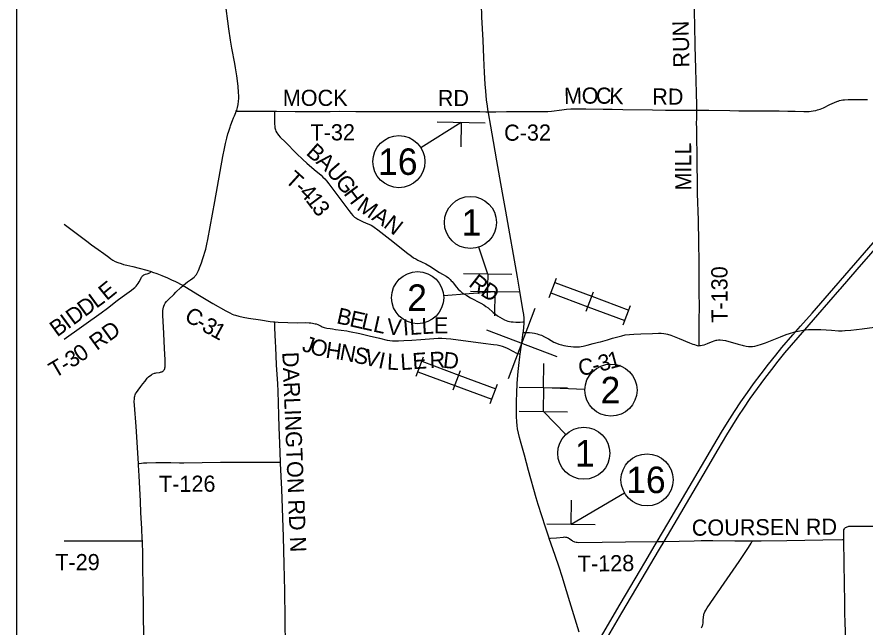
# Model space of a CAD drawing. Extents: x 40529 to 41139, y 15164 to 15584.
# Drawn here: x 40528.7 to 40618.2, y 15358.4 to 15422.8 of the extents above; entities that cross this region are included whole.
import ezdxf

# ---------------------------------------------------------------- set-up
doc = ezdxf.new("R2010")
doc.units = 0
for name, color, linetype in [('Default', 7, 'Continuous'), ('GM_X_County_Road', 7, 'Continuous'), ('GM_X_County_Road_Text', 7, 'Continuous'), ('GM_X_Interstate_Route', 7, 'Continuous'), ('GM_X_State_Route', 7, 'Continuous'), ('GM_X_Township_Road', 7, 'Continuous'), ('GM_X_Township_Road_Text', 7, 'Continuous'), ('SC_Scratch1', 7, 'Continuous'), ('SH_Data', 7, 'Continuous'), ('SH_Text', 7, 'Continuous')]:
    doc.layers.add(name, color=color, linetype=linetype)

msp = doc.modelspace()

# ---------------------------------------------------------------- linework, layer by layer
at = {"layer": 'Default'}
for p, q in [((40578.106, 15411.64), (40573.011, 15411.722)), ((40575.559, 15411.681), (40575.518, 15409.134)), ((40580.908, 15395.642), (40575.812, 15395.724)), ((40578.36, 15395.683), (40578.319, 15393.135)), ((40584.861, 15393.226), (40585.613, 15395.258)), ((40585.439, 15394.789), (40589.347, 15393.343)), ((40581.654, 15393.775), (40576.559, 15393.857)), ((40579.106, 15393.816), (40579.066, 15391.269)), ((40585.034, 15393.695), (40588.942, 15392.249)), ((40588.768, 15391.78), (40589.52, 15393.812)), ((40589.347, 15393.343), (40593.254, 15391.896)), ((40592.682, 15390.331), (40593.434, 15392.363)), ((40588.942, 15392.249), (40592.849, 15390.802)), ((40570.813, 15384.915), (40571.565, 15386.947)), ((40571.392, 15386.478), (40575.299, 15385.032)), ((40584.244, 15383.705), (40584.285, 15386.253)), ((40570.987, 15385.384), (40574.894, 15383.938)), ((40574.72, 15383.469), (40575.473, 15385.501)), ((40575.299, 15385.032), (40579.207, 15383.585)), ((40574.894, 15383.938), (40578.801, 15382.491)), ((40578.634, 15382.02), (40579.386, 15384.052)), ((40581.696, 15383.746), (40586.791, 15383.665)), ((40584.244, 15381.174), (40584.285, 15383.722)), ((40581.696, 15381.215), (40586.791, 15381.133)), ((40587.168, 15369.284), (40587.209, 15371.832)), ((40584.62, 15369.325), (40589.716, 15369.243))]:
    msp.add_line(p, q, dxfattribs=at)
at = {"layer": 'GM_X_County_Road'}
for points in [[(40600.43, 15413), (40601.705, 15412.989), (40603.934, 15412.954), (40604.865, 15412.943), (40605.796, 15412.943), (40606.821, 15412.939), (40609.142, 15412.923), (40610.071, 15412.895), (40610.816, 15412.889), (40611.748, 15412.871), (40612.304, 15412.876), (40612.744, 15412.915), (40613.017, 15412.968), (40613.199, 15413.018), (40613.464, 15413.112), (40613.808, 15413.26), (40614.48, 15413.582), (40614.988, 15413.813), (40615.245, 15413.918), (40615.351, 15413.954)], [(40615.351, 15413.954), (40615.377, 15413.963), (40615.505, 15414.008), (40615.684, 15414.051), (40615.865, 15414.082), (40616.049, 15414.1), (40616.42, 15414.121), (40617.414, 15414.121), (40618.462, 15414.136)], [(40578.427, 15412.837), (40578.568, 15412.835), (40578.68, 15412.833), (40579.237, 15412.836), (40580.352, 15412.847), (40581.003, 15412.847), (40582.773, 15412.851), (40584.26, 15412.858), (40584.727, 15412.872), (40585.1, 15412.898), (40586.207, 15413.048), (40586.669, 15413.097), (40587.132, 15413.125), (40587.69, 15413.137), (40588.715, 15413.13), (40590.541, 15413.11), (40590.861, 15413.106), (40591.492, 15413.099), (40592.618, 15413.064), (40595.776, 15413.028), (40597.153, 15413.013), (40598.269, 15413.016), (40599.943, 15413.005), (40600.43, 15413)], [(40533.651, 15400.945), (40536.027, 15399.161), (40536.536, 15398.771), (40537.221, 15398.286), (40537.813, 15397.869), (40538.341, 15397.46), (40538.581, 15397.297), (40538.791, 15397.156), (40539.034, 15397.018), (40539.291, 15396.91), (40539.64, 15396.791), (40539.907, 15396.709), (40540.269, 15396.626), (40540.902, 15396.474), (40541.544, 15396.323), (40542.356, 15396.104), (40542.836, 15395.949)], [(40542.836, 15395.949), (40542.966, 15395.907), (40543.422, 15395.755), (40543.944, 15395.55), (40544.545, 15395.292), (40545.055, 15395.057), (40545.142, 15395.021), (40545.396, 15394.901), (40546.143, 15394.516), (40546.19, 15394.488)], [(40546.19, 15394.488), (40546.547, 15394.281), (40547.736, 15393.544), (40549.341, 15392.593), (40550.715, 15391.803), (40551.124, 15391.581), (40551.375, 15391.461), (40551.547, 15391.393), (40551.721, 15391.334), (40552.082, 15391.244), (40552.536, 15391.148), (40553.086, 15391.051), (40554.377, 15390.854), (40555.39, 15390.691), (40555.759, 15390.648), (40555.885, 15390.64)], [(40555.885, 15390.64), (40556.223, 15390.62), (40558.27, 15390.557), (40559.122, 15390.562), (40559.5, 15390.548), (40559.687, 15390.532), (40559.871, 15390.503), (40560.143, 15390.446), (40560.233, 15390.421), (40560.416, 15390.355), (40560.644, 15390.251), (40560.762, 15390.194), (40560.866, 15390.137), (40561.098, 15390.057), (40561.373, 15389.976), (40561.725, 15389.929), (40561.989, 15389.896), (40562.287, 15389.853), (40563.484, 15389.688), (40563.759, 15389.641), (40564.853, 15389.407), (40565.853, 15389.173), (40566.941, 15388.909), (40567.759, 15388.726), (40568.033, 15388.676), (40568.309, 15388.642), (40568.586, 15388.627), (40568.957, 15388.633), (40569.515, 15388.662), (40570.353, 15388.724), (40571.284, 15388.787), (40572.679, 15388.891), (40573.146, 15388.913), (40573.52, 15388.912), (40573.987, 15388.888), (40574.453, 15388.845), (40577.877, 15388.412), (40578.988, 15388.264), (40579.357, 15388.204), (40579.633, 15388.146), (40579.904, 15388.072), (40580.169, 15387.974), (40580.424, 15387.855), (40581.082, 15387.501), (40581.332, 15387.382), (40581.504, 15387.318), (40581.592, 15387.295), (40581.787, 15387.244)], [(40556.477, 15375.813), (40556.398, 15377.825), (40556.347, 15379.501), (40556.317, 15380.801), (40556.237, 15383.314), (40556.196, 15384.084), (40556.073, 15386.11), (40555.988, 15387.976), (40555.956, 15388.521), (40555.912, 15389.265), (40555.888, 15390.012), (40555.886, 15390.386), (40555.885, 15390.64)], [(40600.695, 15388.131), (40600.762, 15388.133), (40600.851, 15388.143), (40600.999, 15388.181), (40601.207, 15388.236), (40601.56, 15388.356), (40601.821, 15388.464), (40602.088, 15388.577), (40602.262, 15388.64), (40602.491, 15388.706), (40602.561, 15388.72), (40602.729, 15388.736), (40602.909, 15388.741), (40603.199, 15388.722), (40603.464, 15388.663), (40604.827, 15388.282), (40605.232, 15388.183), (40605.332, 15388.162), (40605.391, 15388.14), (40605.504, 15388.124), (40605.656, 15388.09), (40605.916, 15388.056), (40606.176, 15388.045), (40606.317, 15388.052), (40606.574, 15388.095), (40606.833, 15388.157), (40607.274, 15388.29), (40607.715, 15388.442), (40608.237, 15388.641), (40609.271, 15389.067), (40609.88, 15389.304), (40610.234, 15389.426), (40610.681, 15389.56), (40610.891, 15389.617), (40610.94, 15389.63), (40611.135, 15389.673), (40611.502, 15389.746), (40611.857, 15389.797), (40611.909, 15389.805), (40612.245, 15389.837), (40612.619, 15389.855), (40612.993, 15389.854), (40613.552, 15389.829), (40614.668, 15389.757), (40615.411, 15389.712), (40615.675, 15389.709)], [(40615.675, 15389.709), (40615.782, 15389.708), (40616.06, 15389.719), (40616.119, 15389.725)], [(40616.119, 15389.725), (40616.708, 15389.782), (40617.91, 15389.921), (40619.206, 15390.077)], [(40581.787, 15387.244), (40581.957, 15388.436), (40582.116, 15389.529)], [(40582.116, 15389.529), (40582.295, 15389.531), (40582.483, 15389.533), (40582.763, 15389.52), (40583.043, 15389.492), (40583.321, 15389.447), (40583.595, 15389.382), (40583.775, 15389.326), (40584.037, 15389.224), (40584.377, 15389.068), (40584.791, 15388.851), (40585.359, 15388.514), (40585.611, 15388.39), (40585.873, 15388.291), (40586.14, 15388.207), (40586.402, 15388.148), (40586.827, 15388.074), (40587.139, 15388.029), (40587.416, 15388.014), (40587.677, 15387.995), (40587.871, 15388.006), (40588.053, 15388.024), (40588.236, 15388.049), (40588.429, 15388.084), (40588.864, 15388.197), (40589.493, 15388.343), (40590.07, 15388.499), (40590.263, 15388.543), (40591.009, 15388.756), (40591.538, 15388.909), (40592.24, 15389.112), (40592.512, 15389.186), (40592.872, 15389.263), (40593.336, 15389.317), (40593.802, 15389.351), (40594.548, 15389.378), (40595.758, 15389.419), (40596.411, 15389.44), (40596.692, 15389.438), (40596.973, 15389.416), (40597.159, 15389.386), (40597.342, 15389.345), (40597.7, 15389.24), (40598.051, 15389.114), (40598.57, 15388.902), (40599.682, 15388.429), (40600.017, 15388.299), (40600.192, 15388.242), (40600.391, 15388.168), (40600.599, 15388.128), (40600.695, 15388.131)], [(40557.06, 15352.563), (40557.051, 15353.293), (40557.032, 15355.102), (40557.008, 15356.31), (40556.927, 15362.258), (40556.867, 15365.056), (40556.803, 15367.946), (40556.615, 15372.978), (40556.482, 15375.68), (40556.477, 15375.813)]]:
    msp.add_lwpolyline(points, dxfattribs=at)
at = {"layer": 'GM_X_Interstate_Route'}
for points in [[(40590.313, 15356.129), (40592.533, 15359.907), (40594.572, 15363.358), (40596.511, 15366.652), (40596.989, 15367.464), (40601.1, 15374.443), (40602.71, 15377.173), (40603.608, 15378.7), (40604.24, 15379.734), (40604.89, 15380.758), (40605.405, 15381.536), (40606.09, 15382.537), (40606.846, 15383.601), (40607.618, 15384.654), (40608.352, 15385.619), (40609.045, 15386.498), (40609.754, 15387.364), (40611.857, 15389.797), (40613.229, 15391.385), (40615.552, 15394.059), (40615.619, 15394.135), (40617.395, 15396.161), (40623.387, 15403.059)], [(40589.027, 15355.179), (40592.36, 15360.837), (40594.502, 15364.443), (40594.972, 15365.247), (40596.057, 15367.095), (40596.267, 15367.451), (40597.382, 15369.342), (40599.653, 15373.196), (40602.247, 15377.617), (40603.054, 15378.981), (40603.689, 15380.012), (40604.439, 15381.192), (40605.108, 15382.201), (40605.795, 15383.199), (40606.445, 15384.108), (40607.223, 15385.155), (40608.019, 15386.189), (40608.774, 15387.136), (40609.428, 15387.925), (40610.582, 15389.268), (40610.891, 15389.617), (40611.384, 15390.173), (40612.61, 15391.577), (40615.364, 15394.74), (40615.607, 15395.019), (40620.689, 15400.855)]]:
    msp.add_lwpolyline(points, dxfattribs=at)
at = {"layer": 'GM_X_State_Route'}
for points in [[(40581.944, 15392.788), (40581.76, 15393.891), (40581.515, 15395.362), (40580.266, 15402.335), (40580.001, 15403.896), (40579.751, 15405.27), (40579.332, 15407.654), (40578.982, 15409.674), (40578.693, 15411.327), (40578.448, 15412.703), (40578.427, 15412.837), (40578.332, 15413.439), (40578.248, 15414.085), (40578.151, 15415.011), (40578.093, 15415.754), (40578.025, 15416.963), (40577.956, 15418.542), (40577.871, 15420.404), (40577.756, 15422.824), (40577.695, 15424.219), (40577.632, 15425.523), (40577.531, 15427.664), (40577.508, 15428.064)], [(40582.116, 15389.529), (40582.132, 15389.635), (40582.184, 15390.099), (40582.21, 15390.473), (40582.213, 15390.651), (40582.215, 15390.753), (40582.206, 15391.034), (40582.174, 15391.407), (40582.122, 15391.777), (40581.944, 15392.788)], [(40581.787, 15387.244), (40581.957, 15388.436), (40582.116, 15389.529)], [(40581.424, 15383.062), (40581.488, 15384.178), (40581.572, 15385.386), (40581.634, 15386.035), (40581.746, 15386.96), (40581.787, 15387.244)], [(40588.017, 15357.876), (40587.039, 15361.083), (40586.677, 15362.238), (40586.21, 15363.751), (40585.9, 15364.728), (40585.483, 15365.964), (40584.85, 15367.777), (40584.839, 15367.811), (40584.457, 15368.96), (40583.69, 15371.355), (40583.476, 15372.067), (40582.675, 15374.936), (40582.233, 15376.554), (40581.882, 15377.811), (40581.714, 15378.44), (40581.608, 15378.893), (40581.52, 15379.349), (40581.466, 15379.715), (40581.434, 15380.084), (40581.411, 15380.641), (40581.394, 15381.666), (40581.398, 15382.317), (40581.424, 15383.062)]]:
    msp.add_lwpolyline(points, dxfattribs=at)
at = {"layer": 'GM_X_Township_Road'}
msp.add_line((40551.415, 15411.915), (40551.525, 15412.19), dxfattribs=at)
for points in [[(40551.816, 15412.907), (40551.854, 15413.01), (40551.934, 15413.273), (40552.018, 15413.614), (40552.063, 15413.945), (40552.08, 15414.223), (40552.079, 15414.502), (40552.058, 15414.872), (40551.996, 15415.521), (40551.859, 15416.63), (40551.739, 15417.458), (40551.657, 15417.913), (40551.351, 15419.556), (40551.213, 15420.383), (40551.041, 15421.58), (40550.631, 15424.534), (40550.405, 15426.102), (40550.306, 15426.935), (40550.252, 15427.686), (40550.241, 15427.94)], [(40600.43, 15413), (40600.429, 15413.536), (40600.398, 15414.842), (40600.336, 15417.355), (40600.262, 15419.776), (40600.26, 15420.242), (40600.253, 15420.428), (40600.237, 15421.358), (40600.229, 15422.101), (40600.221, 15422.19), (40600.2, 15423.111), (40600.181, 15424.712)], [(40600.695, 15388.131), (40600.696, 15388.352), (40600.698, 15388.724), (40600.689, 15389.843), (40600.695, 15390.031), (40600.691, 15390.084), (40600.697, 15390.736), (40600.704, 15391.198), (40600.711, 15391.849), (40600.725, 15392.312), (40600.715, 15392.749), (40600.701, 15393.265), (40600.706, 15395.026), (40600.692, 15396.981), (40600.67, 15399.033), (40600.626, 15401.385), (40600.533, 15404.205), (40600.494, 15408.472), (40600.46, 15409.923), (40600.434, 15410.839), (40600.434, 15411.119), (40600.427, 15411.584), (40600.434, 15412.142), (40600.43, 15413)], [(40551.525, 15412.19), (40551.614, 15412.411), (40551.758, 15412.75), (40551.816, 15412.907)], [(40551.816, 15412.907), (40551.943, 15412.906), (40552.71, 15412.898), (40554.013, 15412.887), (40555.849, 15412.882)], [(40555.849, 15412.882), (40556.062, 15412.881), (40558.018, 15412.867), (40559.042, 15412.866), (40560.16, 15412.862), (40561.742, 15412.872), (40562.673, 15412.878), (40564.441, 15412.852), (40565.926, 15412.851), (40567.319, 15412.852), (40568.808, 15412.858), (40571.574, 15412.857), (40572.689, 15412.848), (40574.734, 15412.854), (40577.523, 15412.849), (40578.171, 15412.84), (40578.427, 15412.837)], [(40555.849, 15412.882), (40555.851, 15411.51), (40555.869, 15411.304), (40555.893, 15411.128), (40555.939, 15410.931), (40556, 15410.768), (40556.097, 15410.593), (40556.184, 15410.474), (40556.272, 15410.352), (40556.463, 15410.147), (40556.993, 15409.621), (40558.183, 15408.432), (40558.855, 15407.783), (40559.27, 15407.406), (40560.052, 15406.739), (40560.762, 15406.132), (40560.966, 15405.94), (40561.161, 15405.739), (40561.345, 15405.529), (40561.576, 15405.236), (40562.746, 15403.661), (40563.699, 15402.391), (40563.933, 15402.099), (40564.122, 15401.891), (40564.309, 15401.714), (40564.435, 15401.615), (40564.648, 15401.485), (40564.922, 15401.343), (40565.196, 15401.216), (40565.462, 15401.107), (40566.051, 15400.851), (40566.234, 15400.757), (40566.387, 15400.653), (40566.758, 15400.376), (40568.36, 15399.12), (40569.795, 15397.973), (40570.31, 15397.573), (40570.539, 15397.408), (40570.772, 15397.287), (40570.985, 15397.173), (40571.375, 15396.99), (40571.83, 15396.758), (40572.235, 15396.516), (40573.259, 15395.869), (40573.579, 15395.685), (40573.99, 15395.463), (40574.227, 15395.29), (40574.39, 15395.122), (40574.504, 15394.983), (40574.6, 15394.89), (40574.725, 15394.749), (40575.071, 15394.308), (40575.257, 15394.097), (40575.462, 15393.904), (40575.68, 15393.727), (40575.908, 15393.562), (40576.145, 15393.411), (40576.551, 15393.182), (40577.625, 15392.62), (40577.945, 15392.434), (40578.175, 15392.28), (40578.395, 15392.111), (40578.953, 15391.619), (40579.17, 15391.441), (40579.398, 15391.276), (40579.634, 15391.125), (40579.877, 15390.985), (40580.13, 15390.86), (40580.304, 15390.79), (40580.483, 15390.732), (40580.667, 15390.688), (40580.852, 15390.657), (40581.039, 15390.639), (40581.319, 15390.625), (40581.785, 15390.627), (40582.065, 15390.643), (40582.213, 15390.651)], [(40550.936, 15410.488), (40550.985, 15410.66), (40551.153, 15411.194), (40551.204, 15411.34)], [(40551.204, 15411.34), (40551.337, 15411.722), (40551.415, 15411.915)], [(40546.19, 15394.488), (40546.236, 15394.528), (40546.451, 15394.707), (40546.675, 15394.876), (40546.979, 15395.091), (40547.209, 15395.247), (40547.354, 15395.36), (40547.42, 15395.422), (40547.482, 15395.488), (40547.594, 15395.632), (40547.69, 15395.788), (40547.805, 15396.056), (40548.008, 15396.539), (40548.136, 15396.89), (40548.288, 15397.345), (40548.587, 15398.319), (40548.709, 15398.86), (40548.809, 15399.329), (40549.562, 15403.343), (40550.408, 15408.114), (40550.556, 15408.94), (40550.672, 15409.488), (40550.807, 15410.031), (40550.936, 15410.488)], [(40533.651, 15388.803), (40537.53, 15391.609), (40538.204, 15392.106), (40539.225, 15392.911), (40539.749, 15393.297), (40540.74, 15393.995), (40540.966, 15394.165), (40541.108, 15394.288), (40541.23, 15394.41), (40541.343, 15394.542), (40541.45, 15394.695), (40541.547, 15394.86), (40541.717, 15395.192), (40541.81, 15395.35), (40541.864, 15395.424), (40541.923, 15395.491), (40541.99, 15395.551), (40542.064, 15395.602), (40542.143, 15395.644), (40542.227, 15395.679), (40542.404, 15395.732), (40542.673, 15395.814), (40542.762, 15395.888), (40542.836, 15395.949)], [(40541.474, 15375.668), (40541.42, 15376.815), (40541.237, 15379.602), (40541.077, 15381.832), (40541.043, 15382.232), (40541.047, 15382.512), (40541.066, 15382.692), (40541.099, 15382.815), (40541.137, 15382.943), (40541.18, 15383.042), (40541.26, 15383.184), (40541.436, 15383.445), (40541.721, 15383.813), (40541.944, 15384.113), (40542.183, 15384.399), (40542.411, 15384.7), (40542.539, 15384.837), (40542.676, 15384.96), (40542.844, 15385.058), (40542.921, 15385.109), (40543.002, 15385.151), (40543.172, 15385.211), (40543.259, 15385.237), (40543.348, 15385.257), (40543.717, 15385.308), (40543.807, 15385.326), (40543.893, 15385.35), (40543.974, 15385.384), (40544.049, 15385.429), (40544.114, 15385.486), (40544.17, 15385.553), (40544.216, 15385.628), (40544.252, 15385.71), (40544.279, 15385.796), (40544.296, 15385.884), (40544.306, 15385.974), (40544.312, 15386.157), (40544.289, 15386.62), (40544.219, 15387.827), (40544.151, 15389.405), (40544.06, 15391.36), (40544.055, 15391.641), (40544.062, 15391.828), (40544.084, 15392.015), (40544.122, 15392.201), (40544.148, 15392.291), (40544.219, 15392.467), (40544.313, 15392.631), (40544.429, 15392.781), (40544.646, 15392.992), (40545.224, 15393.551), (40545.427, 15393.774), (40545.957, 15394.282), (40546.19, 15394.488)], [(40541.474, 15375.668), (40541.569, 15375.687), (40541.796, 15375.734), (40542.009, 15375.76), (40542.383, 15375.773), (40543.307, 15375.787), (40544.519, 15375.787), (40544.886, 15375.795), (40545.81, 15375.763), (40546.271, 15375.768), (40550.156, 15375.819), (40552.569, 15375.822), (40554.799, 15375.825), (40555.728, 15375.827), (40556.325, 15375.816), (40556.477, 15375.813)], [(40541.894, 15367.528), (40541.885, 15367.702), (40541.838, 15368.817), (40541.749, 15370.491), (40541.686, 15371.701), (40541.542, 15374.395), (40541.481, 15375.512), (40541.474, 15375.668)], [(40615.981, 15368.667), (40616.025, 15368.772), (40616.084, 15368.851), (40616.155, 15368.92), (40616.234, 15368.974), (40616.327, 15369.012), (40616.419, 15369.044), (40616.513, 15369.063), (40616.702, 15369.079), (40619.033, 15369.084), (40621.174, 15369.099), (40623.087, 15369.122)], [(40615.972, 15367.653), (40615.956, 15368.528), (40615.981, 15368.667)], [(40533.651, 15367.538), (40535.716, 15367.506), (40537.764, 15367.509), (40538.609, 15367.513), (40541.29, 15367.509), (40541.668, 15367.513), (40541.753, 15367.518), (40541.894, 15367.528)], [(40542.226, 15352.725), (40542.182, 15353.94), (40542.133, 15355.523), (40542.058, 15358.13), (40542.03, 15359.062), (40542.013, 15359.991), (40542.001, 15361.103), (40541.984, 15362.221), (40541.976, 15363.057), (40541.934, 15364.452), (40541.931, 15365.291), (40541.935, 15366.497), (40541.919, 15367.053), (40541.894, 15367.528)], [(40584.85, 15367.777), (40584.999, 15367.791), (40585.635, 15367.85), (40586.379, 15367.923), (40586.474, 15367.926), (40586.569, 15367.923), (40586.668, 15367.909), (40586.757, 15367.888), (40586.836, 15367.859), (40586.911, 15367.818), (40586.991, 15367.765), (40587.211, 15367.594), (40587.287, 15367.544), (40587.367, 15367.501), (40587.45, 15367.463), (40587.537, 15367.432), (40587.711, 15367.388), (40587.81, 15367.367), (40587.984, 15367.352), (40592.92, 15367.424), (40596.267, 15367.451), (40596.329, 15367.452), (40596.552, 15367.454), (40596.95, 15367.463), (40596.989, 15367.464), (40600.179, 15367.532), (40600.92, 15367.542), (40602.129, 15367.54), (40604.458, 15367.52), (40606.323, 15367.526)], [(40600.929, 15358.321), (40601.013, 15358.485), (40601.047, 15358.571), (40601.072, 15358.661), (40601.102, 15358.845), (40601.123, 15359.123), (40601.142, 15359.498), (40601.173, 15359.682), (40601.193, 15359.772), (40601.22, 15359.86), (40601.296, 15360.03), (40601.383, 15360.195), (40601.534, 15360.43), (40603.326, 15363.043), (40603.957, 15363.967), (40604.924, 15365.338), (40605.913, 15366.812), (40606.191, 15367.283), (40606.263, 15367.416), (40606.323, 15367.526)], [(40606.323, 15367.526), (40607.252, 15367.53), (40609.952, 15367.559), (40613.768, 15367.627), (40615.817, 15367.652), (40615.972, 15367.653)], [(40616.499, 15338.489), (40616.492, 15339.715), (40616.475, 15340.804), (40616.454, 15341.242), (40616.424, 15342.354), (40616.409, 15343.004), (40616.382, 15344.397), (40616.347, 15346.072), (40616.321, 15348.027), (40616.304, 15349.424), (40616.268, 15351.378), (40616.198, 15353.891), (40616.154, 15355.942), (40616.146, 15356.129), (40616.129, 15357.897), (40616.11, 15358.92), (40616.092, 15359.846), (40616.075, 15360.309), (40616.066, 15361.427), (40616.056, 15362.638), (40616.007, 15365.525), (40615.983, 15367.2), (40615.972, 15367.653)]]:
    msp.add_lwpolyline(points, dxfattribs=at)
at = {"layer": 'SC_Scratch1'}
msp.add_lwpolyline([(40528.651, 15584.313), (41138.651, 15584.313), (41138.651, 15164.313), (40528.651, 15164.313)], close=True, dxfattribs=at)
at = {"layer": 'SH_Data'}
for p, q in [((40575.559, 15411.681), (40571.316, 15409.023)), ((40578.36, 15395.683), (40577.408, 15398.536)), ((40579.106, 15393.816), (40573.706, 15393.407)), ((40580.543, 15384.666), (40583.357, 15392.107)), ((40578.23, 15389.794), (40585.67, 15386.979)), ((40584.284, 15383.705), (40588.632, 15383.541)), ((40584.244, 15381.174), (40586.599, 15378.742)), ((40587.168, 15369.284), (40592.81, 15372.574))]:
    msp.add_line(p, q, dxfattribs=at)
at = {"layer": 'SH_Text'}
for centre in [(40568.986, 15407.563), (40576.538, 15401.145), (40570.964, 15393.199), (40591.38, 15383.437), (40588.511, 15376.766), (40595.185, 15373.96)]:
    msp.add_circle(centre, 2.75, dxfattribs=at)

# ---------------------------------------------------------------- texts
at = {"layer": 'GM_X_County_Road_Text'}
for s, height, rotation, p in [('M', 1.706, 1.43852, (40586.447, 15413.647)), ('O', 1.706, 359.69764, (40588.284, 15413.693)), ('C', 1.706, 359.55117, (40589.785, 15413.685)), ('K', 1.706, 358.2184, (40591.175, 15413.674)), ('RD', 1.7063, 359.50921, (40595.728, 15413.6)), ('C-32', 1.7063, 0.34061, (40580.099, 15409.764)), ('C', 1.706, 328.60652, (40546.215, 15390.881)), ('B', 1.706, 347.30524, (40562.317, 15390.512)), ('E', 1.706, 347.30837, (40563.685, 15390.204)), ('L', 1.706, 347.30572, (40564.93, 15389.923)), ('-', 1.706, 329.3345, (40547.432, 15390.139)), ('3', 1.706, 330.41392, (40548.065, 15389.764)), ('L', 1.706, 347.35925, (40566.176, 15389.642)), ('V', 1.706, 355.15864, (40567.668, 15389.325)), ('I', 1.706, 4.76304, (40569.471, 15389.198)), ('L', 1.706, 3.7525, (40570.161, 15389.256)), ('L', 1.706, 3.67525, (40571.434, 15389.339)), ('E', 1.706, 0.35571, (40572.682, 15389.42)), ('1', 1.706, 331.28831, (40549.004, 15389.231)), ('J', 1.706, 341.29724, (40558.647, 15387.624)), ('O', 1.706, 343.86335, (40559.485, 15387.342)), ('H', 1.706, 351.7322, (40561.178, 15386.871)), ('N', 1.706, 349.6124, (40562.647, 15386.657)), ('S', 1.706, 347.57736, (40564.108, 15386.39)), ('DARLINGTON RD N', 1.70629, 272.31764, (40556.668, 15387.441)), ('V', 1.706, 346.97453, (40565.228, 15386.143)), ('I', 1.706, 347.87609, (40566.72, 15385.798)), ('L', 1.706, 357.18018, (40567.704, 15385.612)), ('L', 1.706, 3.7565, (40569.193, 15385.551)), ('E', 1.706, 3.73539, (40570.466, 15385.635)), ('R', 1.706, 2.17455, (40572.252, 15385.751)), ('D', 1.706, 353.54235, (40573.584, 15385.807)), ('3', 1.706, 14.7498, (40590.277, 15385.38)), ('1', 1.706, 15.13893, (40591.306, 15385.651)), ('C', 1.706, 10.52303, (40588.087, 15384.917)), ('-', 1.706, 14.58122, (40589.594, 15385.202))]:
    msp.add_text(s, height=height, rotation=rotation, dxfattribs=at).set_placement(p)
at = {"layer": 'GM_X_Township_Road_Text'}
for s, height, rotation, p in [('RUN', 1.7063, 91.21891, (40599.671, 15417.513)), ('MOCK', 1.7063, 0.00171, (40556.72, 15413.45)), ('RD', 1.7063, 0.00001, (40573.09, 15413.424)), ('T-32', 1.7063, 0.3442, (40559.654, 15409.792)), ('B', 1.706, 318.61765, (40559.094, 15408.378)), ('MILL', 1.7063, 90.27759, (40599.871, 15404.515)), ('A', 1.706, 318.30415, (40560.144, 15407.453)), ('T', 1.706, 317.73756, (40556.872, 15405.489)), ('U', 1.706, 311.03515, (40561.225, 15406.495)), ('G', 1.706, 306.75187, (40562.189, 15405.389)), ('-', 1.706, 319.60454, (40557.862, 15404.591)), ('H', 1.706, 306.76701, (40563.088, 15404.185)), ('4', 1.706, 315.85741, (40558.374, 15404.157)), ('1', 1.706, 306.81786, (40559.081, 15403.478)), ('3', 1.706, 307.07725, (40559.716, 15402.63)), ('M', 1.706, 325.70022, (40564.43, 15402.558)), ('A', 1.706, 328.10211, (40566.025, 15401.472)), ('N', 1.706, 322.10425, (40567.261, 15400.706)), ('T-130', 1.7063, 90.27959, (40603.704, 15390.557)), ('E', 1.706, 39.04425, (40538.128, 15392.824)), ('R', 1.706, 321.9857, (40576.258, 15394.487)), ('D', 1.706, 327.36409, (40577.503, 15393.524)), ('L', 1.706, 36.32669, (40537.031, 15392.014)), ('D', 1.706, 36.17119, (40535.815, 15391.125)), ('I', 1.706, 36.16749, (40534.037, 15389.825)), ('D', 1.706, 36.17135, (40534.603, 15390.239)), ('B', 1.706, 35.93354, (40532.897, 15388.999)), ('RD', 1.7063, 35.99842, (40537.079, 15387.56)), ('0', 1.706, 35.09421, (40535.363, 15386.328)), ('3', 1.706, 32.892, (40534.421, 15385.717)), ('T', 1.706, 30.4625, (40532.655, 15384.664)), ('-', 1.706, 31.30275, (40533.779, 15385.325)), ('T-126', 1.7063, 0.2784, (40543.657, 15372.679)), ('COURSEN RD', 1.7063, 0.43238, (40599.92, 15368.055)), ('T-29', 1.7063, 0.00001, (40532.699, 15364.421)), ('T-128', 1.7063, 0.83558, (40587.886, 15364.246))]:
    msp.add_text(s, height=height, rotation=rotation, dxfattribs=at).set_placement(p)
at = {"layer": 'SH_Text'}
for s, p in [('16', (40566.789, 15406.163)), ('1', (40575.601, 15399.745)), ('2', (40569.864, 15391.799)), ('2', (40590.281, 15382.037)), ('1', (40587.575, 15375.366)), ('16', (40592.988, 15372.56))]:
    msp.add_text(s, height=2.8, dxfattribs=at).set_placement(p)

doc.saveas('drawing.dxf')
